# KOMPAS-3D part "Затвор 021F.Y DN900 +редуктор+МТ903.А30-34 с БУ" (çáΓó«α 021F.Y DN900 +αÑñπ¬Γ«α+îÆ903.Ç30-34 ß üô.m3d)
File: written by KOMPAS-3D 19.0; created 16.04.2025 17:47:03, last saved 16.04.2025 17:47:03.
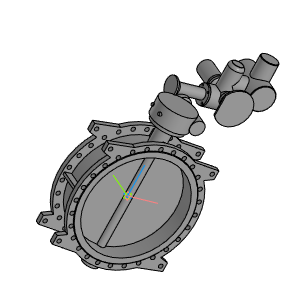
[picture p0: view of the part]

Document properties: Полное имя файла: Затвор 021F.Y DN900 +редуктор+МТ903.А30-34 с БУ.a3d

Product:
- Part/product: Затвор 021F.Y DN900 +редуктор+МТ903.А30-34 с БУ
    Масса: 1066.01

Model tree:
1. Операция без истории:1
